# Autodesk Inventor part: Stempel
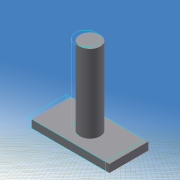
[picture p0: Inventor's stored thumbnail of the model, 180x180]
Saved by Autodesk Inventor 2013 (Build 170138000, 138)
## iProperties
Created: 2012-09
Part Number: Stempel
Material: Allgemein
Document SubType Name: Modeling
Designer: tvs
Mass: 104.13 g
Surface Area: 212.475 cm^2
Volume: 104.13 cm^3
Density: 1 g/cm^3
Author: tvs
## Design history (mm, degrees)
sketch "Skizze1"
  geometry: C1 r 13.126 at (0, 0); 1 further point
  constraints: 1 centre point, 1 coincident
extrude "Extrusion1" new body sketch "Skizze1" distance "d0" = 100; taper "d1" = 0 deg
sketch "Skizze2"
  geometry: L1 (-50, 25)-(50, 25); L2 (50, 25)-(50, -25); L3 (50, -25)-(-50, -25); L4 (-50, -25)-(-50, 25); C1 r 13.126 at (0, 0) reference; 2 further points
  constraints: 8 end point, 2 midpoint, 2 parallel, 1 horizontal, 1 horizontal alignment, 1 perpendicular, 1 vertical alignment
  dimensions: "d2" = 50 distance between parallel lines of L3 L1; "d4" = 100 distance of L1.start L1.end
extrude "Extrusion2" join sketch "Skizze2" distance "d5" = 10; taper "d6" = 0 deg
node "Volumenkörper1"
